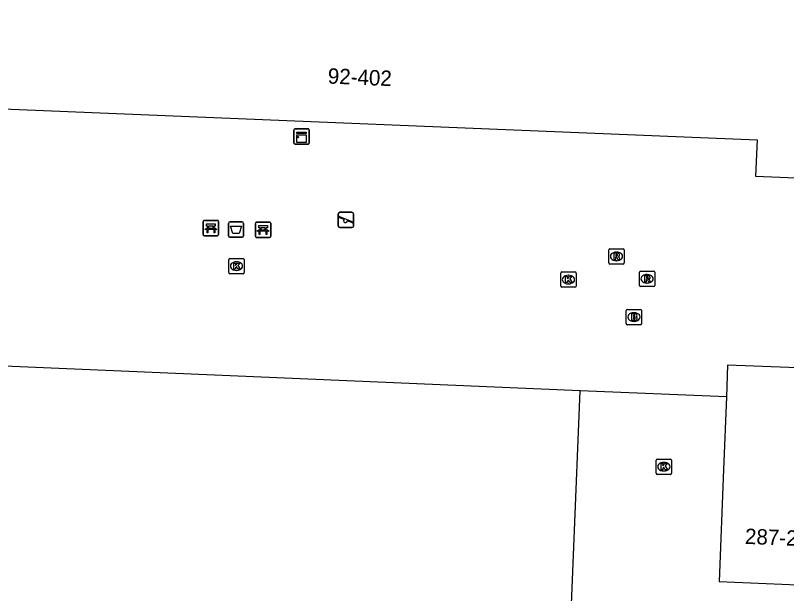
# Model space of a CAD drawing. Extents: x 160891 to 161384, y 386490 to 386907.
# Drawn here: x 161090.7 to 161140.9, y 386697.3 to 386734.9 of the extents above; entities that cross this region are included whole.
import ezdxf

# ---------------------------------------------------------------- set-up
doc = ezdxf.new("R2010")
doc.units = 0
for name, color, linetype in [('IMGEO_Afvalbak', 7, 'Continuous'), ('IMGEO_Bank', 7, 'Continuous'), ('IMGEO_Brandkraan', 7, 'Continuous'), ('IMGEO_Kast', 7, 'Continuous'), ('IMGEO_Kolk', 7, 'Continuous'), ('IMGEO_Pand', 7, 'Continuous'), ('IMGEO_Pand_nummerreeks', 7, 'Continuous'), ('IMGEO_Rioolput', 7, 'Continuous'), ('IMGEO_Speelvoorziening', 7, 'Continuous'), ('IMGEO_Voetgangersgebied_open', 7, 'Continuous')]:
    doc.layers.add(name, color=color, linetype=linetype)

msp = doc.modelspace()

# ---------------------------------------------------------------- linework, layer by layer
at = {"layer": 'IMGEO_Afvalbak'}
for p, q in [((161104.559, 386720.582), (161104.559, 386721.382)), ((161104.559, 386721.382), (161104.559, 386720.582)), ((161104.659, 386721.482), (161105.449, 386721.482)), ((161105.449, 386721.482), (161104.659, 386721.482)), ((161105.549, 386721.382), (161105.549, 386720.582)), ((161105.549, 386720.582), (161105.549, 386721.382)), ((161105.449, 386720.482), (161104.659, 386720.482)), ((161104.659, 386720.482), (161105.449, 386720.482))]:
    msp.add_line(p, q, dxfattribs=at)
msp.add_lwpolyline([(161104.702, 386721.196), (161105.406, 386721.196), (161105.257, 386720.726), (161104.851, 386720.726), (161104.702, 386721.196)], dxfattribs=at)
for centre, start, end in [((161104.659, 386721.382), 90, 180), ((161104.659, 386721.382), 90, 180), ((161105.449, 386721.382), 0, 90), ((161105.449, 386721.382), 360, 90), ((161104.659, 386720.582), 180, 270), ((161104.659, 386720.582), 180, 270), ((161105.449, 386720.582), 270, 0), ((161105.449, 386720.582), 270, 0)]:
    msp.add_arc(centre, 0.1, start, end, dxfattribs=at)
at = {"layer": 'IMGEO_Bank'}
for p, q in [((161102.921, 386720.656), (161102.921, 386721.497)), ((161102.921, 386721.497), (161102.921, 386720.656)), ((161102.996, 386721.581), (161103.837, 386721.581)), ((161103.837, 386721.581), (161102.996, 386721.581)), ((161103.921, 386721.506), (161103.921, 386720.665)), ((161103.921, 386720.665), (161103.921, 386721.506)), ((161106.318, 386720.544), (161106.318, 386721.385)), ((161106.318, 386721.385), (161106.318, 386720.544)), ((161106.393, 386721.469), (161107.234, 386721.469)), ((161107.234, 386721.469), (161106.393, 386721.469)), ((161107.318, 386721.394), (161107.318, 386720.553)), ((161107.318, 386720.553), (161107.318, 386721.394)), ((161103.618, 386720.979), (161103.225, 386720.979)), ((161103.23, 386721.087), (161103.23, 386721.193)), ((161103.274, 386721.193), (161103.274, 386721.087)), ((161103.562, 386721.199), (161103.28, 386721.199)), ((161103.28, 386721.081), (161103.562, 386721.081)), ((161103.568, 386721.087), (161103.568, 386721.193)), ((161103.612, 386721.193), (161103.612, 386721.087)), ((161107.015, 386720.867), (161106.622, 386720.867)), ((161106.627, 386720.975), (161106.627, 386721.081)), ((161106.671, 386721.081), (161106.671, 386720.975)), ((161106.959, 386721.087), (161106.677, 386721.087)), ((161106.677, 386720.969), (161106.959, 386720.969)), ((161106.965, 386720.975), (161106.965, 386721.081)), ((161107.009, 386721.081), (161107.009, 386720.975)), ((161103.846, 386720.581), (161103.005, 386720.581)), ((161103.005, 386720.581), (161103.846, 386720.581)), ((161107.243, 386720.469), (161106.402, 386720.469)), ((161106.402, 386720.469), (161107.243, 386720.469))]:
    msp.add_line(p, q, dxfattribs=at)
for points in [[(161103.224, 386721.199), (161103.138, 386721.199), (161103.138, 386721.36), (161103.701, 386721.36), (161103.701, 386721.199), (161103.618, 386721.199)], [(161106.621, 386721.087), (161106.535, 386721.087), (161106.535, 386721.248), (161107.098, 386721.248), (161107.098, 386721.087), (161107.015, 386721.087)], [(161103.168, 386720.979), (161103.026, 386720.979), (161103.138, 386721.081), (161103.224, 386721.081)], [(161103.218, 386720.972), (161103.218, 386720.765), (161103.175, 386720.765), (161103.175, 386720.972)], [(161103.618, 386721.081), (161103.701, 386721.081), (161103.813, 386720.979), (161103.674, 386720.979)], [(161103.668, 386720.972), (161103.668, 386720.765), (161103.624, 386720.765), (161103.624, 386720.972)], [(161106.565, 386720.867), (161106.423, 386720.867), (161106.535, 386720.969), (161106.621, 386720.969)], [(161106.615, 386720.86), (161106.615, 386720.653), (161106.572, 386720.653), (161106.572, 386720.86)], [(161107.015, 386720.969), (161107.098, 386720.969), (161107.21, 386720.867), (161107.071, 386720.867)], [(161107.065, 386720.86), (161107.065, 386720.653), (161107.021, 386720.653), (161107.021, 386720.86)]]:
    msp.add_lwpolyline(points, dxfattribs=at)
for centre, radius, start, end in [((161102.999, 386721.503), 0.0779, 92.4484, 184.2845), ((161102.999, 386721.503), 0.0779, 92.4484, 184.2845), ((161103.843, 386721.503), 0.0779, 2.4484, 94.2845), ((161103.843, 386721.503), 0.0779, 2.4484, 94.2845), ((161106.396, 386721.391), 0.0779, 92.4484, 184.2845), ((161106.396, 386721.391), 0.0779, 92.4484, 184.2845), ((161107.24, 386721.391), 0.0779, 2.4484, 94.2845), ((161107.24, 386721.391), 0.0779, 2.4484, 94.2845), ((161103.168, 386720.972), 0.00671, 2.8957, 87.1043), ((161103.225, 386720.972), 0.00671, 92.8957, 177.1043), ((161103.223, 386721.192), 0.00671, 2.8957, 87.1043), ((161103.223, 386721.088), 0.00671, 272.8957, 357.1043), ((161103.28, 386721.192), 0.00671, 92.8957, 177.1043), ((161103.28, 386721.088), 0.00671, 182.8957, 267.1043), ((161103.562, 386721.192), 0.00671, 2.8957, 87.1043), ((161103.562, 386721.088), 0.00671, 272.8957, 357.1043), ((161103.619, 386721.192), 0.00671, 92.8957, 177.1043), ((161103.619, 386721.088), 0.00671, 182.8957, 267.1043), ((161103.617, 386720.972), 0.00671, 2.8957, 87.1043), ((161103.674, 386720.972), 0.00671, 92.8957, 177.1043), ((161106.565, 386720.86), 0.00671, 2.8957, 87.1043), ((161106.622, 386720.86), 0.00671, 92.8957, 177.1043), ((161106.62, 386721.08), 0.00671, 2.8957, 87.1043), ((161106.62, 386720.976), 0.00671, 272.8957, 357.1043), ((161106.677, 386721.08), 0.00671, 92.8957, 177.1043), ((161106.677, 386720.976), 0.00671, 182.8957, 267.1043), ((161106.959, 386721.08), 0.00671, 2.8957, 87.1043), ((161106.959, 386720.976), 0.00671, 272.8957, 357.1043), ((161107.016, 386721.08), 0.00671, 92.8957, 177.1043), ((161107.016, 386720.976), 0.00671, 182.8957, 267.1043), ((161107.014, 386720.86), 0.00671, 2.8957, 87.1043), ((161107.071, 386720.86), 0.00671, 92.8957, 177.1043), ((161102.999, 386720.659), 0.0779, 182.4484, 274.2845), ((161102.999, 386720.659), 0.0779, 182.4484, 274.2845), ((161103.843, 386720.659), 0.0779, 272.4484, 4.2845), ((161103.843, 386720.659), 0.0779, 272.4484, 4.2845), ((161106.396, 386720.547), 0.0779, 182.4484, 274.2845), ((161106.396, 386720.547), 0.0779, 182.4484, 274.2845), ((161107.24, 386720.547), 0.0779, 272.4484, 4.2845), ((161107.24, 386720.547), 0.0779, 272.4484, 4.2845)]:
    msp.add_arc(centre, radius, start, end, dxfattribs=at)
at = {"layer": 'IMGEO_Brandkraan'}
for p, q in [((161130.468, 386714.863), (161130.468, 386715.715)), ((161130.543, 386715.789), (161131.395, 386715.789)), ((161131.469, 386715.715), (161131.469, 386714.863)), ((161130.956, 386715.569), (161130.981, 386715.569)), ((161131.395, 386714.789), (161130.543, 386714.789)), ((161130.979, 386715.009), (161130.954, 386715.009))]:
    msp.add_line(p, q, dxfattribs=at)
for points in [[(161130.468, 386714.863), (161130.468, 386715.715)], [(161130.543, 386715.789), (161131.395, 386715.789)], [(161131.469, 386715.715), (161131.469, 386714.863)], [(161130.816, 386715.489), (161130.816, 386715.089), (161131.029, 386715.089)], [(161131.047, 386715.489), (161130.816, 386715.489)], [(161130.995, 386715.408), (161130.941, 386715.408), (161130.941, 386715.332)], [(161130.941, 386715.332), (161130.994, 386715.332)], [(161131.003, 386715.256), (161130.941, 386715.256), (161130.941, 386715.175)], [(161131.395, 386714.789), (161130.543, 386714.789)], [(161130.941, 386715.175), (161131.003, 386715.175)]]:
    msp.add_lwpolyline(points, dxfattribs=at)
for centre, radius, start, end in [((161130.545, 386715.713), 0.0765, 91.552, 178.448), ((161130.545, 386715.713), 0.0765, 91.552, 178.448), ((161131.393, 386715.713), 0.0765, 1.552, 88.448), ((161131.393, 386715.713), 0.0765, 1.552, 88.448), ((161130.996, 386715.37), 0.0379, 267.8285, 90.9355), ((161131.004, 386715.215), 0.0404, 269.8759, 90.5077), ((161131.051, 386715.344), 0.145, 59.4692, 91.5367), ((161131.076, 386715.391), 0.0922, 285.5137, 58.1501), ((161131.081, 386715.199), 0.105, 301.3115, 78.989), ((161130.545, 386714.865), 0.0765, 181.552, 268.448), ((161130.545, 386714.865), 0.0765, 181.552, 268.448), ((161131.035, 386715.34), 0.251, 268.6676, 293.5347), ((161131.393, 386714.865), 0.0765, 271.552, 358.448), ((161131.393, 386714.865), 0.0765, 271.552, 358.448)]:
    msp.add_arc(centre, radius, start, end, dxfattribs=at)
for centre, major_axis, ratio, start_param, end_param in [((161130.955, 386715.289), (-0.387, 0.002), 0.722429, 4.712389, 7.853982), ((161130.98, 386715.289), (-0.39, 0.002), 0.717154, 1.570796, 4.712389)]:
    msp.add_ellipse(centre, major_axis=major_axis, ratio=ratio, start_param=start_param, end_param=end_param, dxfattribs=at)
at = {"layer": 'IMGEO_Kast'}
for p, q in [((161108.828, 386726.606), (161108.828, 386727.447)), ((161108.828, 386727.447), (161108.828, 386726.606)), ((161108.903, 386727.531), (161109.744, 386727.531)), ((161109.744, 386727.531), (161108.903, 386727.531)), ((161109.828, 386727.456), (161109.828, 386726.615)), ((161109.828, 386726.615), (161109.828, 386727.456)), ((161109.753, 386726.531), (161108.912, 386726.531)), ((161108.912, 386726.531), (161109.753, 386726.531))]:
    msp.add_line(p, q, dxfattribs=at)
for points in [[(161109.023, 386727.321), (161109.623, 386727.321), (161109.623, 386727.236), (161109.023, 386727.236), (161109.023, 386727.321)], [(161109.023, 386727.146), (161109.623, 386727.146), (161109.623, 386726.657), (161109.023, 386726.657), (161109.023, 386727.146)]]:
    msp.add_lwpolyline(points, dxfattribs=at)
msp.add_circle((161109.107, 386726.995), 0.0377, dxfattribs=at)
for centre, start, end in [((161108.906, 386727.453), 92.4484, 184.2845), ((161108.906, 386727.453), 92.4484, 184.2845), ((161109.75, 386727.453), 2.4484, 94.2845), ((161109.75, 386727.453), 2.4484, 94.2845), ((161108.906, 386726.609), 182.4484, 274.2845), ((161108.906, 386726.609), 182.4484, 274.2845), ((161109.75, 386726.609), 272.4484, 4.2845), ((161109.75, 386726.609), 272.4484, 4.2845)]:
    msp.add_arc(centre, 0.0779, start, end, dxfattribs=at)
at = {"layer": 'IMGEO_Kolk'}
for p, q in [((161104.588, 386718.179), (161104.588, 386719.031)), ((161104.663, 386719.105), (161105.515, 386719.105)), ((161105.076, 386718.885), (161105.101, 386718.885)), ((161105.589, 386719.031), (161105.589, 386718.179)), ((161105.099, 386718.325), (161105.074, 386718.325)), ((161126.274, 386718.229), (161127.126, 386718.229)), ((161105.515, 386718.105), (161104.663, 386718.105)), ((161126.199, 386717.303), (161126.199, 386718.155)), ((161126.687, 386718.009), (161126.712, 386718.009)), ((161127.2, 386718.155), (161127.2, 386717.303)), ((161127.126, 386717.229), (161126.274, 386717.229)), ((161126.71, 386717.449), (161126.685, 386717.449)), ((161132.412, 386705.126), (161132.412, 386705.978)), ((161132.487, 386706.052), (161133.339, 386706.052)), ((161132.9, 386705.832), (161132.925, 386705.832)), ((161133.413, 386705.978), (161133.413, 386705.126)), ((161132.923, 386705.272), (161132.898, 386705.272)), ((161133.339, 386705.052), (161132.487, 386705.052))]:
    msp.add_line(p, q, dxfattribs=at)
for points in [[(161104.588, 386718.179), (161104.588, 386719.031)], [(161104.663, 386719.105), (161105.515, 386719.105)], [(161104.909, 386718.805), (161105.032, 386718.805), (161105.032, 386718.654), (161105.162, 386718.805), (161105.326, 386718.805), (161105.18, 386718.654), (161105.333, 386718.405), (161105.181, 386718.405), (161105.096, 386718.569), (161105.032, 386718.502), (161105.032, 386718.405), (161104.909, 386718.405), (161104.909, 386718.805)], [(161105.589, 386719.031), (161105.589, 386718.179)], [(161126.274, 386718.229), (161127.126, 386718.229)], [(161105.515, 386718.105), (161104.663, 386718.105)], [(161126.199, 386717.303), (161126.199, 386718.155)], [(161126.52, 386717.929), (161126.643, 386717.929), (161126.643, 386717.778), (161126.773, 386717.929), (161126.937, 386717.929), (161126.791, 386717.778), (161126.944, 386717.529), (161126.792, 386717.529), (161126.707, 386717.693), (161126.643, 386717.626), (161126.643, 386717.529), (161126.52, 386717.529), (161126.52, 386717.929)], [(161127.2, 386718.155), (161127.2, 386717.303)], [(161127.126, 386717.229), (161126.274, 386717.229)], [(161132.412, 386705.126), (161132.412, 386705.978)], [(161132.487, 386706.052), (161133.339, 386706.052)], [(161132.733, 386705.752), (161132.856, 386705.752), (161132.856, 386705.601), (161132.986, 386705.752), (161133.15, 386705.752), (161133.004, 386705.601), (161133.157, 386705.352), (161133.005, 386705.352), (161132.92, 386705.516), (161132.856, 386705.449), (161132.856, 386705.352), (161132.733, 386705.352), (161132.733, 386705.752)], [(161133.413, 386705.978), (161133.413, 386705.126)], [(161133.339, 386705.052), (161132.487, 386705.052)]]:
    msp.add_lwpolyline(points, dxfattribs=at)
for centre, start, end in [((161104.665, 386719.029), 91.552, 178.448), ((161104.665, 386719.029), 91.552, 178.448), ((161105.513, 386719.029), 1.552, 88.448), ((161105.513, 386719.029), 1.552, 88.448), ((161126.276, 386718.153), 91.552, 178.448), ((161126.276, 386718.153), 91.552, 178.448), ((161127.124, 386718.153), 1.552, 88.448), ((161127.124, 386718.153), 1.552, 88.448), ((161104.665, 386718.181), 181.552, 268.448), ((161104.665, 386718.181), 181.552, 268.448), ((161105.513, 386718.181), 271.552, 358.448), ((161105.513, 386718.181), 271.552, 358.448), ((161126.276, 386717.305), 181.552, 268.448), ((161126.276, 386717.305), 181.552, 268.448), ((161127.124, 386717.305), 271.552, 358.448), ((161127.124, 386717.305), 271.552, 358.448), ((161132.489, 386705.976), 91.552, 178.448), ((161132.489, 386705.976), 91.552, 178.448), ((161133.337, 386705.976), 1.552, 88.448), ((161133.337, 386705.976), 1.552, 88.448), ((161132.489, 386705.128), 181.552, 268.448), ((161132.489, 386705.128), 181.552, 268.448), ((161133.337, 386705.128), 271.552, 358.448), ((161133.337, 386705.128), 271.552, 358.448)]:
    msp.add_arc(centre, 0.0765, start, end, dxfattribs=at)
for centre, major_axis, ratio, start_param, end_param in [((161105.075, 386718.605), (-0.387, 0.002), 0.722429, 4.712389, 7.853982), ((161105.1, 386718.605), (-0.39, 0.002), 0.717154, 1.570796, 4.712389), ((161126.686, 386717.729), (-0.387, 0.002), 0.722429, 4.712389, 7.853982), ((161126.711, 386717.729), (-0.39, 0.002), 0.717154, 1.570796, 4.712389), ((161132.899, 386705.552), (-0.387, 0.002), 0.722429, 4.712389, 7.853982), ((161132.924, 386705.552), (-0.39, 0.002), 0.717154, 1.570796, 4.712389)]:
    msp.add_ellipse(centre, major_axis=major_axis, ratio=ratio, start_param=start_param, end_param=end_param, dxfattribs=at)
at = {"layer": 'IMGEO_Pand'}
for points in [[(161067.82, 386734.914), (161068.128, 386734.901), (161081.411, 386726.666), (161089.223, 386726.344), (161089.335, 386728.855), (161138.981, 386726.813), (161138.885, 386724.445), (161161.551, 386723.521)], [(161127.462, 386710.495), (161080.851, 386712.475), (161066.929, 386705.356), (161066.624, 386705.366)], [(161147.81, 386709.63), (161147.892, 386711.738), (161137.065, 386712.159), (161136.985, 386710.09)], [(161128.539, 386559.143), (161129.239, 386576.285), (161129.528, 386583.353), (161129.817, 386590.42), (161130.314, 386602.572), (161130.741, 386613.029), (161129.102, 386613.11), (161129.234, 386616.884), (161123.653, 386617.125), (161124.235, 386631.392), (161124.542, 386638.918), (161124.93, 386648.428), (161125.316, 386657.891), (161125.805, 386669.885), (161127.462, 386710.495)], [(161136.985, 386710.09), (161136.801, 386705.368), (161136.518, 386698.078), (161143.664, 386697.789), (161147.34, 386697.641), (161147.455, 386700.577), (161147.81, 386709.63)]]:
    msp.add_lwpolyline(points, dxfattribs=at)
at = {"layer": 'IMGEO_Rioolput'}
for p, q in [((161129.405, 386719.735), (161130.257, 386719.735)), ((161129.33, 386718.809), (161129.33, 386719.661)), ((161129.818, 386719.515), (161129.843, 386719.515)), ((161130.331, 386719.661), (161130.331, 386718.809)), ((161130.257, 386718.735), (161129.405, 386718.735)), ((161129.841, 386718.955), (161129.816, 386718.955)), ((161131.397, 386718.277), (161132.249, 386718.277)), ((161131.322, 386717.351), (161131.322, 386718.203)), ((161131.81, 386718.057), (161131.835, 386718.057)), ((161132.323, 386718.203), (161132.323, 386717.351)), ((161132.249, 386717.277), (161131.397, 386717.277)), ((161131.833, 386717.497), (161131.808, 386717.497))]:
    msp.add_line(p, q, dxfattribs=at)
for points in [[(161129.405, 386719.735), (161130.257, 386719.735)], [(161129.33, 386718.809), (161129.33, 386719.661)], [(161129.919, 386719.433), (161129.667, 386719.435), (161129.667, 386719.035)], [(161129.845, 386719.354), (161129.791, 386719.354), (161129.791, 386719.273)], [(161129.791, 386719.273), (161129.843, 386719.273)], [(161130.331, 386719.661), (161130.331, 386718.809)], [(161130.257, 386718.735), (161129.405, 386718.735)], [(161129.667, 386719.035), (161129.791, 386719.035), (161129.791, 386719.197), (161129.802, 386719.197)], [(161129.849, 386719.168), (161129.92, 386719.035), (161130.06, 386719.035), (161129.995, 386719.161)], [(161131.397, 386718.277), (161132.249, 386718.277)], [(161131.322, 386717.351), (161131.322, 386718.203)], [(161131.911, 386717.975), (161131.659, 386717.977), (161131.659, 386717.577)], [(161131.659, 386717.577), (161131.783, 386717.577), (161131.783, 386717.739), (161131.794, 386717.739)], [(161131.837, 386717.896), (161131.783, 386717.896), (161131.783, 386717.815)], [(161131.783, 386717.815), (161131.835, 386717.815)], [(161132.323, 386718.203), (161132.323, 386717.351)], [(161132.249, 386717.277), (161131.397, 386717.277)], [(161131.841, 386717.71), (161131.912, 386717.577), (161132.052, 386717.577), (161131.987, 386717.703)]]:
    msp.add_lwpolyline(points, dxfattribs=at)
for centre, radius, start, end in [((161129.407, 386719.659), 0.0765, 91.552, 178.448), ((161129.407, 386719.659), 0.0765, 91.552, 178.448), ((161130.255, 386719.659), 0.0765, 1.552, 88.448), ((161130.255, 386719.659), 0.0765, 1.552, 88.448), ((161129.827, 386719.462), 0.19, 274.7715, 282.9687), ((161129.851, 386719.258), 0.0964, 77.0061, 93.1865), ((161129.865, 386719.315), 0.0378, 276.6634, 79.6772), ((161129.918, 386719.323), 0.109, 350.3612, 89.416), ((161129.916, 386719.323), 0.112, 277.5842, 350.9817), ((161129.407, 386718.811), 0.0765, 181.552, 268.448), ((161129.407, 386718.811), 0.0765, 181.552, 268.448), ((161129.801, 386719.144), 0.0533, 26.0293, 88.6989), ((161129.9, 386719.108), 0.108, 29.5134, 73.7905), ((161130.255, 386718.811), 0.0765, 271.552, 358.448), ((161130.255, 386718.811), 0.0765, 271.552, 358.448), ((161131.399, 386718.201), 0.0765, 91.552, 178.448), ((161131.399, 386718.201), 0.0765, 91.552, 178.448), ((161132.247, 386718.201), 0.0765, 1.552, 88.448), ((161132.247, 386718.201), 0.0765, 1.552, 88.448), ((161131.793, 386717.686), 0.0533, 26.0293, 88.6989), ((161131.819, 386718.004), 0.19, 274.7715, 282.9687), ((161131.843, 386717.8), 0.0964, 77.0061, 93.1865), ((161131.857, 386717.857), 0.0378, 276.6634, 79.6772), ((161131.91, 386717.865), 0.109, 350.3612, 89.416), ((161131.908, 386717.865), 0.112, 277.5842, 350.9817), ((161131.892, 386717.65), 0.108, 29.5134, 73.7905), ((161131.399, 386717.353), 0.0765, 181.552, 268.448), ((161131.399, 386717.353), 0.0765, 181.552, 268.448), ((161132.247, 386717.353), 0.0765, 271.552, 358.448), ((161132.247, 386717.353), 0.0765, 271.552, 358.448)]:
    msp.add_arc(centre, radius, start, end, dxfattribs=at)
for centre, major_axis, ratio, start_param, end_param in [((161129.817, 386719.235), (-0.387, 0.002), 0.722429, 4.712389, 7.853982), ((161129.842, 386719.235), (-0.39, 0.002), 0.717154, 1.570796, 4.712389), ((161131.809, 386717.777), (-0.387, 0.002), 0.722429, 4.712389, 7.853982), ((161131.834, 386717.777), (-0.39, 0.002), 0.717154, 1.570796, 4.712389)]:
    msp.add_ellipse(centre, major_axis=major_axis, ratio=ratio, start_param=start_param, end_param=end_param, dxfattribs=at)
at = {"layer": 'IMGEO_Speelvoorziening'}
for p, q in [((161111.718, 386721.21), (161111.718, 386722.01)), ((161111.718, 386722.01), (161111.718, 386721.21)), ((161112.101, 386721.638), (161111.762, 386721.775)), ((161111.787, 386721.835), (161112.663, 386721.482)), ((161111.818, 386722.11), (161112.608, 386722.11)), ((161112.608, 386722.11), (161111.818, 386722.11)), ((161112.708, 386722.01), (161112.708, 386721.21)), ((161112.708, 386721.21), (161112.708, 386722.01)), ((161112.639, 386721.422), (161112.299, 386721.559)), ((161112.608, 386721.11), (161111.818, 386721.11)), ((161111.818, 386721.11), (161112.608, 386721.11))]:
    msp.add_line(p, q, dxfattribs=at)
for centre, radius, start, end in [((161111.818, 386722.01), 0.1, 90, 180), ((161111.818, 386722.01), 0.1, 90, 180), ((161111.775, 386721.805), 0.0327, 68.078, 248.078), ((161112.608, 386722.01), 0.1, 0, 90), ((161112.608, 386722.01), 0.1, 360, 90), ((161112.18, 386721.548), 0.12, 130.9928, 5.1632), ((161112.651, 386721.452), 0.0327, 248.078, 68.078), ((161111.818, 386721.21), 0.1, 180, 270), ((161111.818, 386721.21), 0.1, 180, 270), ((161112.608, 386721.21), 0.1, 270, 0), ((161112.608, 386721.21), 0.1, 270, 0)]:
    msp.add_arc(centre, radius, start, end, dxfattribs=at)
at = {"layer": 'IMGEO_Voetgangersgebied_open'}
msp.add_lwpolyline([(161136.985, 386710.09), (161127.462, 386710.495)], dxfattribs=at)

# ---------------------------------------------------------------- texts
at = {"layer": 'IMGEO_Pand_nummerreeks'}
for s, rotation, p in [('92-402', 357.6451, (161111.019, 386730.485)), ('287-289', 357.6853, (161138.181, 386700.533))]:
    msp.add_text(s, height=1, rotation=rotation, dxfattribs=at).set_placement(p)

doc.saveas('drawing.dxf')
